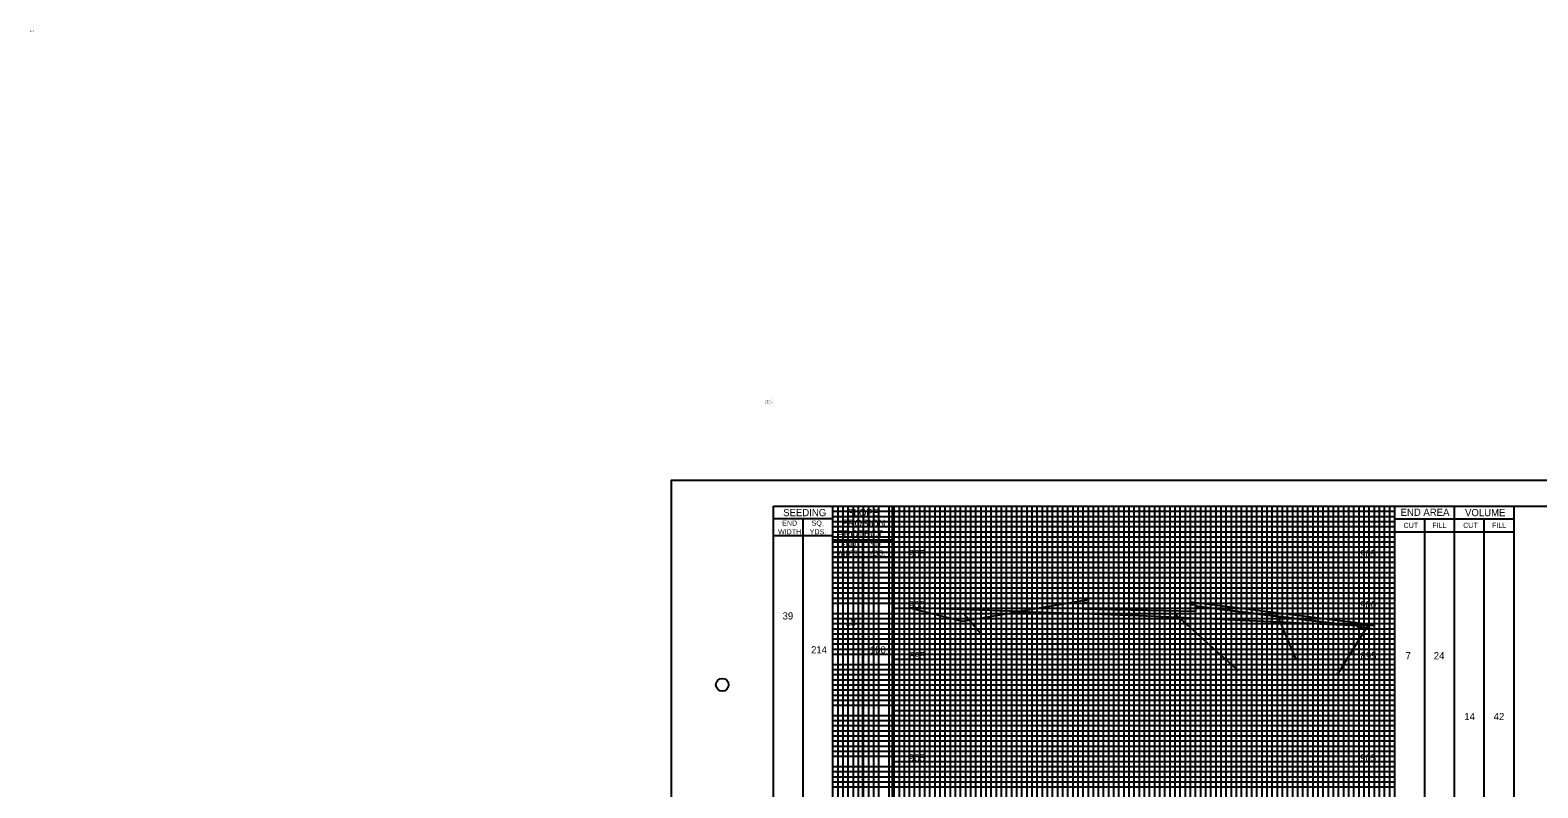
# Model space of a CAD drawing. Extents: x -73 to 160, y -2 to 1877.
# Drawn here: x -72.7 to 74.8, y 1802.4 to 1876.6 of the extents above; entities that cross this region are included whole.
import ezdxf

# ---------------------------------------------------------------- set-up
doc = ezdxf.new("R2010")
doc.units = 0
for name, color, linetype in [('DR_P_Flood_Boundary', 7, 'Continuous'), ('GK_Cells', 7, 'Continuous'), ('RD_X_Fence', 7, 'Continuous'), ('TX_X_5', 7, 'Continuous'), ('UT_P_Water_Cells', 7, 'Continuous'), ('XS_P_Pavt_Surface', 7, 'Continuous'), ('XS_P_Text_Info', 7, 'Continuous'), ('XS_X_Ground_Line', 7, 'Continuous')]:
    doc.layers.add(name, color=color, linetype=linetype)

msp = doc.modelspace()

# ---------------------------------------------------------------- linework, layer by layer
at = {"layer": 'DR_P_Flood_Boundary'}
for p, q in [((15.83, 1725), (15.83, 1830)), ((20.83, 1725), (20.83, 1830)), ((25.83, 1725), (25.83, 1830)), ((30.83, 1725), (30.83, 1830)), ((35.83, 1725), (35.83, 1830)), ((40.83, 1725), (40.83, 1830)), ((45.83, 1725), (45.83, 1830)), ((50.83, 1725), (50.83, 1830)), ((55.83, 1725), (55.83, 1830)), ((5.83, 1825), (60.83, 1825)), ((11.66, 1820), (60.83, 1820)), ((11.66, 1815), (60.83, 1815)), ((11.66, 1810), (60.83, 1810)), ((11.66, 1805), (60.83, 1805))]:
    msp.add_line(p, q, dxfattribs=at)
at = {"layer": 'GK_Cells'}
msp.add_lwpolyline([(0, 1830), (157.5, 1830), (157.5, 1725), (0, 1725)], close=True, dxfattribs=at)
msp.add_circle((-5, 1812.5), 0.625, dxfattribs=at)
at = {"layer": 'RD_X_Fence'}
for p, q in [((13.31, 1820.05), (18.49, 1818.75)), ((24.1, 1819.68), (13.31, 1820.05)), ((18.49, 1818.75), (24.1, 1819.68)), ((30.83, 1820.81), (24.1, 1819.68)), ((30.33, 1819.9), (30.33, 1820.57)), ((30.33, 1820.57), (30.83, 1820.56)), ((41.33, 1819.68), (30.33, 1819.9)), ((58.83, 1818.33), (40.83, 1820.61)), ((40.83, 1820.61), (40.83, 1820.5)), ((40.83, 1820.5), (40.83, 1820.36)), ((40.83, 1820.36), (41.33, 1820.35)), ((41.33, 1820.35), (41.33, 1820.21)), ((41.33, 1820.21), (41.33, 1819.68)), ((55.97, 1818.37), (41.33, 1820.21)), ((41.33, 1820.21), (55.97, 1818.37)), ((18.63, 1819.49), (20.28, 1817.57)), ((35.83, 1819.29), (42.33, 1818.99)), ((39.26, 1819.47), (45.49, 1813.89)), ((49.29, 1819.38), (51.1, 1815.09)), ((58.13, 1818.21), (55.27, 1813.64)), ((55.97, 1818.37), (57.11, 1818.32)), ((57.1, 1818.22), (58.83, 1818)), ((58.83, 1818.33), (57.11, 1818.32)), ((57.11, 1818.32), (58.83, 1818.33)), ((58.83, 1818), (58.83, 1818.33))]:
    msp.add_line(p, q, dxfattribs=at)
for points in [[(24.1, 1819.68), (29.33, 1819.51), (35.83, 1819.29)], [(30.83, 1820.56), (30.83, 1820.7), (30.83, 1820.81)], [(42.33, 1818.99), (50.81, 1818.59), (54.18, 1818.44), (55.97, 1818.37)], [(57.11, 1818.32), (57.1, 1818.22)]]:
    msp.add_lwpolyline(points, dxfattribs=at)
at = {"layer": 'TX_X_5'}
msp.add_lwpolyline([(-10, 1722.5), (160, 1722.5), (160, 1832.5), (-10, 1832.5)], close=True, dxfattribs=at)
at = {"layer": 'UT_P_Water_Cells'}
for p, q in [((6.33, 1725), (6.33, 1830)), ((6.83, 1725), (6.83, 1830)), ((7.33, 1725), (7.33, 1830)), ((7.83, 1725), (7.83, 1830)), ((8.33, 1725), (8.33, 1830)), ((8.83, 1725), (8.83, 1830)), ((9.33, 1725), (9.33, 1830)), ((9.83, 1725), (9.83, 1830)), ((10.33, 1725), (10.33, 1830)), ((11.33, 1725), (11.33, 1830)), ((11.83, 1725), (11.83, 1830)), ((12.33, 1725), (12.33, 1830)), ((12.83, 1725), (12.83, 1830)), ((13.33, 1725), (13.33, 1830)), ((13.83, 1725), (13.83, 1830)), ((14.33, 1725), (14.33, 1830)), ((14.83, 1725), (14.83, 1830)), ((15.33, 1725), (15.33, 1830)), ((16.33, 1725), (16.33, 1830)), ((16.83, 1725), (16.83, 1830)), ((17.33, 1725), (17.33, 1830)), ((17.83, 1725), (17.83, 1830)), ((18.33, 1725), (18.33, 1830)), ((18.83, 1725), (18.83, 1830)), ((19.33, 1725), (19.33, 1830)), ((19.83, 1725), (19.83, 1830)), ((20.33, 1725), (20.33, 1830)), ((21.33, 1725), (21.33, 1830)), ((21.83, 1725), (21.83, 1830)), ((22.33, 1725), (22.33, 1830)), ((22.83, 1725), (22.83, 1830)), ((23.33, 1725), (23.33, 1830)), ((23.83, 1725), (23.83, 1830)), ((24.33, 1725), (24.33, 1830)), ((24.83, 1725), (24.83, 1830)), ((25.33, 1725), (25.33, 1830)), ((26.33, 1725), (26.33, 1830)), ((26.83, 1725), (26.83, 1830)), ((27.33, 1725), (27.33, 1830)), ((27.83, 1725), (27.83, 1830)), ((28.33, 1725), (28.33, 1830)), ((28.83, 1725), (28.83, 1830)), ((29.33, 1725), (29.33, 1830)), ((29.83, 1725), (29.83, 1830)), ((30.33, 1725), (30.33, 1830)), ((31.33, 1725), (31.33, 1830)), ((31.83, 1725), (31.83, 1830)), ((32.33, 1725), (32.33, 1830)), ((32.83, 1725), (32.83, 1830)), ((33.33, 1725), (33.33, 1830)), ((33.83, 1725), (33.83, 1830)), ((34.33, 1725), (34.33, 1830)), ((34.83, 1725), (34.83, 1830)), ((35.33, 1725), (35.33, 1830)), ((36.33, 1725), (36.33, 1830)), ((36.83, 1725), (36.83, 1830)), ((37.33, 1725), (37.33, 1830)), ((37.83, 1725), (37.83, 1830)), ((38.33, 1725), (38.33, 1830)), ((38.83, 1725), (38.83, 1830)), ((39.33, 1725), (39.33, 1830)), ((39.83, 1725), (39.83, 1830)), ((40.33, 1725), (40.33, 1830)), ((41.33, 1725), (41.33, 1830)), ((41.83, 1725), (41.83, 1830)), ((42.33, 1725), (42.33, 1830)), ((42.83, 1725), (42.83, 1830)), ((43.33, 1725), (43.33, 1830)), ((43.83, 1725), (43.83, 1830)), ((44.33, 1725), (44.33, 1830)), ((44.83, 1725), (44.83, 1830)), ((45.33, 1725), (45.33, 1830)), ((46.33, 1725), (46.33, 1830)), ((46.83, 1725), (46.83, 1830)), ((47.33, 1725), (47.33, 1830)), ((47.83, 1725), (47.83, 1830)), ((48.33, 1725), (48.33, 1830)), ((48.83, 1725), (48.83, 1830)), ((49.33, 1725), (49.33, 1830)), ((49.83, 1725), (49.83, 1830)), ((50.33, 1725), (50.33, 1830)), ((51.33, 1725), (51.33, 1830)), ((51.83, 1725), (51.83, 1830)), ((52.33, 1725), (52.33, 1830)), ((52.83, 1725), (52.83, 1830)), ((53.33, 1725), (53.33, 1830)), ((53.83, 1725), (53.83, 1830)), ((54.33, 1725), (54.33, 1830)), ((54.83, 1725), (54.83, 1830)), ((55.33, 1725), (55.33, 1830)), ((56.33, 1725), (56.33, 1830)), ((56.83, 1725), (56.83, 1830)), ((57.33, 1725), (57.33, 1830)), ((57.83, 1725), (57.83, 1830)), ((58.33, 1725), (58.33, 1830)), ((58.83, 1725), (58.83, 1830)), ((59.33, 1725), (59.33, 1830)), ((59.83, 1725), (59.83, 1830)), ((60.33, 1725), (60.33, 1830)), ((5.83, 1829.5), (60.83, 1829.5)), ((5.83, 1829), (60.83, 1829)), ((5.83, 1828.5), (60.83, 1828.5)), ((5.83, 1828), (60.83, 1828)), ((5.83, 1827.5), (60.83, 1827.5)), ((5.83, 1827), (60.83, 1827)), ((5.83, 1826.5), (60.83, 1826.5)), ((5.83, 1826), (60.83, 1826)), ((5.83, 1825.5), (60.83, 1825.5)), ((5.83, 1824.5), (60.83, 1824.5)), ((5.83, 1824), (60.83, 1824)), ((5.83, 1823.5), (60.83, 1823.5)), ((5.83, 1823), (60.83, 1823)), ((5.83, 1822.5), (60.83, 1822.5)), ((5.83, 1822), (60.83, 1822)), ((5.83, 1821.5), (60.83, 1821.5)), ((5.83, 1821), (60.83, 1821)), ((5.83, 1820.5), (60.83, 1820.5)), ((5.83, 1819.5), (60.83, 1819.5)), ((5.83, 1819), (60.83, 1819)), ((5.83, 1818.5), (60.83, 1818.5)), ((5.83, 1818), (60.83, 1818)), ((5.83, 1817.5), (60.83, 1817.5)), ((5.83, 1817), (60.83, 1817)), ((5.83, 1816.5), (60.83, 1816.5)), ((5.83, 1816), (60.83, 1816)), ((5.83, 1815.5), (60.83, 1815.5)), ((5.83, 1814.5), (60.83, 1814.5)), ((5.83, 1814), (60.83, 1814)), ((5.83, 1813.5), (60.83, 1813.5)), ((5.83, 1813), (60.83, 1813)), ((5.83, 1812.5), (60.83, 1812.5)), ((5.83, 1812), (60.83, 1812)), ((5.83, 1811.5), (60.83, 1811.5)), ((5.83, 1811), (60.83, 1811)), ((5.83, 1810.5), (60.83, 1810.5)), ((5.83, 1809.5), (60.83, 1809.5)), ((5.83, 1809), (60.83, 1809)), ((5.83, 1808.5), (60.83, 1808.5)), ((5.83, 1808), (60.83, 1808)), ((5.83, 1807.5), (60.83, 1807.5)), ((5.83, 1807), (60.83, 1807)), ((5.83, 1806.5), (60.83, 1806.5)), ((5.83, 1806), (60.83, 1806)), ((5.83, 1805.5), (60.83, 1805.5)), ((5.83, 1804.5), (60.83, 1804.5)), ((5.83, 1804), (60.83, 1804)), ((5.83, 1803.5), (60.83, 1803.5)), ((5.83, 1803), (60.83, 1803)), ((5.83, 1802.5), (60.83, 1802.5))]:
    msp.add_line(p, q, dxfattribs=at)
at = {"layer": 'XS_X_Ground_Line'}
for p, q in [((5.83, 1725), (5.83, 1830)), ((5.83, 1725), (5.83, 1830)), ((11.66, 1725), (11.66, 1830)), ((60.83, 1725), (60.83, 1830)), ((66.67, 1725), (66.67, 1830)), ((72.5, 1725), (72.5, 1830)), ((5.83, 1828.75), (0, 1828.75)), ((2.92, 1725), (2.92, 1828.75)), ((60.83, 1828.75), (72.5, 1828.75)), ((63.75, 1725), (63.75, 1828.75)), ((69.58, 1725), (69.58, 1828.75)), ((5.83, 1827.08), (0, 1827.08)), ((60.83, 1827.5), (72.5, 1827.5)), ((11.66, 1826.67), (5.83, 1826.67)), ((8.75, 1725), (8.75, 1826.67)), ((11.66, 1825), (5.83, 1825))]:
    msp.add_line(p, q, dxfattribs=at)

# ---------------------------------------------------------------- texts
at = {"layer": 'RD_X_Fence'}
for s, p in [('11.9', (-72.76, 1876.49)), ('6.1', (20.16, 1817.5)), ('5.5', (50.94, 1815.02)), ('18.4', (45.3, 1813.82)), ('0.4', (55.1, 1813.57))]:
    msp.add_text(s, height=0.14, dxfattribs=at).set_placement(p)
at = {"layer": 'XS_P_Pavt_Surface'}
for s, p in [('905', (13.27, 1825)), ('905', (57.44, 1825)), ('39', (0.9, 1818.9)), ('900', (13.26, 1820)), ('900', (57.43, 1820)), ('18', (7.05, 1818.28)), ('214', (3.69, 1815.58)), ('100', (9.45, 1815.58)), ('895', (13.3, 1815)), ('895', (57.47, 1815)), ('7', (61.88, 1815)), ('24', (64.64, 1815)), ('14', (67.63, 1809.04)), ('42', (70.5, 1809.04)), ('905', (13.27, 1805)), ('905', (57.44, 1805))]:
    msp.add_text(s, height=0.7, dxfattribs=at).set_placement(p)
at = {"layer": 'XS_P_Text_Info'}
for s, p in [('$FILE$', (-0.7, 1840)), ('$DATE$', (-0.5, 1840)), ('$TIME$', (-0.3, 1840)), ('$USER$', (-0.1, 1840))]:
    msp.add_text(s, height=0.078, rotation=90, dxfattribs=at).set_placement(p)
at = {"layer": 'XS_X_Ground_Line'}
for s, height, p in [('END', 0.5, (0.87, 1828.09)), ('SEEDING', 0.7, (0.96, 1829.02)), ('SQ.', 0.5, (3.75, 1828.09)), ('EROSION', 0.7, (6.65, 1827.98)), ('SLOPE', 0.7, (7.23, 1829.02)), ('END AREA', 0.7, (61.39, 1829.05)), ('VOLUME', 0.7, (67.7, 1829.02)), ('WIDTH', 0.5, (0.46, 1827.24)), ('YDS.', 0.5, (3.56, 1827.24)), ('PROTECT.', 0.7, (6.26, 1826.94)), ('CUT', 0.5, (61.68, 1827.87)), ('FILL', 0.5, (64.5, 1827.87)), ('CUT', 0.5, (67.52, 1827.87)), ('FILL', 0.5, (70.34, 1827.87)), ('WIDTH', 0.5, (6.22, 1825.16)), ('END', 0.5, (6.63, 1826.01)), ('YDS.', 0.5, (9.33, 1825.16)), ('SQ.', 0.5, (9.51, 1826.01))]:
    msp.add_text(s, height=height, dxfattribs=at).set_placement(p)

doc.saveas('drawing.dxf')
